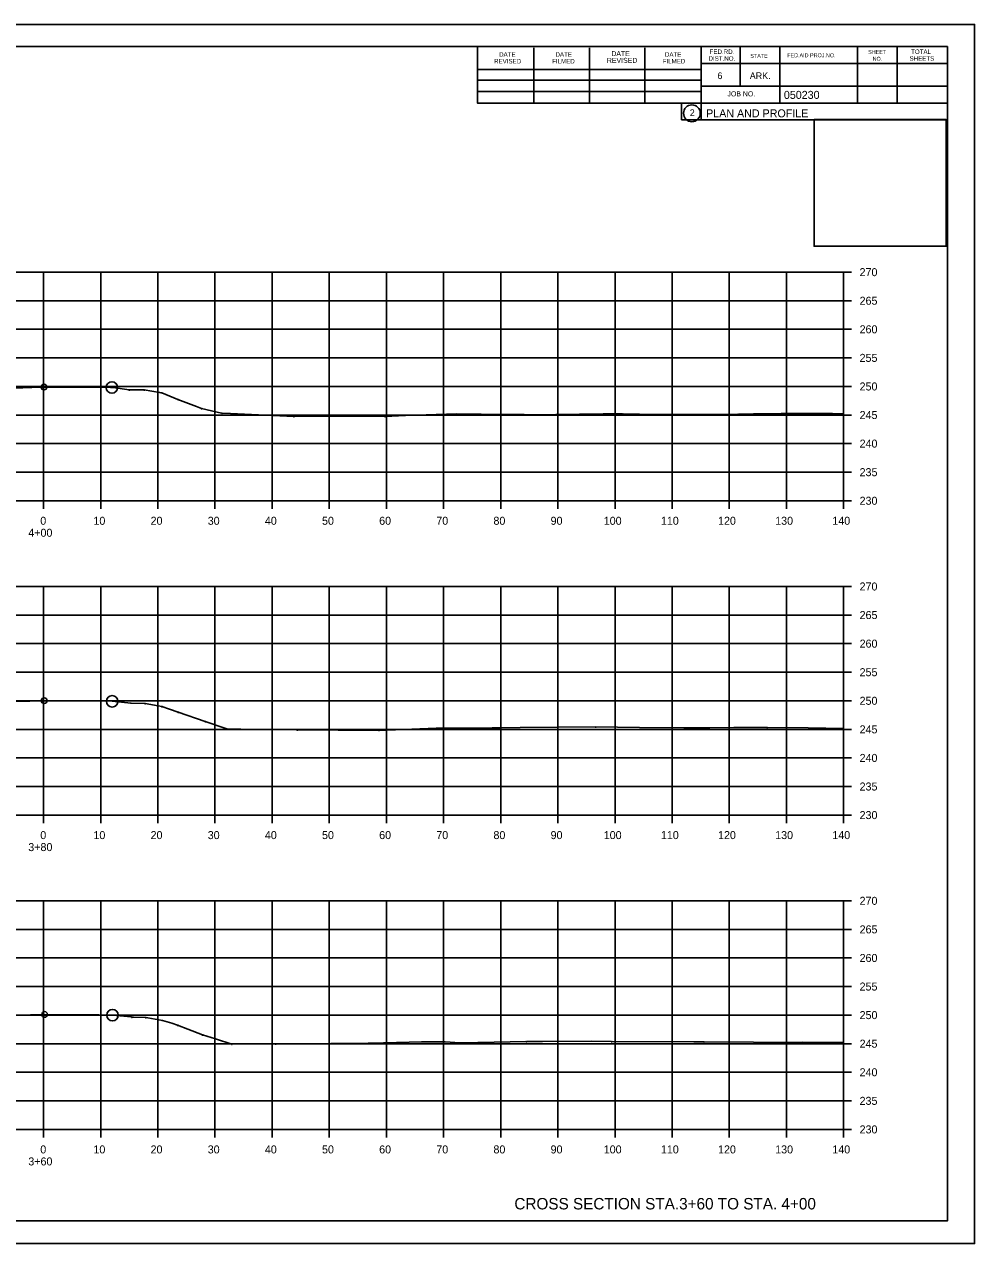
# Model space of a CAD drawing. Extents: x 1300404 to 1323571, y 234004 to 252077.
# Drawn here: x 1315713.9 to 1315880.2, y 241275.1 to 241488.4 of the extents above; entities that cross this region are included whole.
import ezdxf

# ---------------------------------------------------------------- set-up
doc = ezdxf.new("R2010")
doc.units = 0
for name, color, linetype in [('Default', 7, 'Continuous'), ('R_Axis', 7, 'Continuous'), ('R_Axis Annot', 7, 'Continuous'), ('R_Border', 7, 'Continuous'), ('R_Border Prem', 7, 'Continuous'), ('R_Draft', 7, 'Continuous'), ('R_Exist Surface', 7, 'Continuous'), ('R_Grid', 7, 'Continuous'), ('R_No Plot', 7, 'Continuous')]:
    doc.layers.add(name, color=color, linetype=linetype)

msp = doc.modelspace()

# ---------------------------------------------------------------- linework, layer by layer
at = {"layer": 'Default'}
for p, q in [((1315559.28, 241484.55), (1315875.46, 241484.55)), ((1315793.2, 241474.67), (1315793.2, 241484.55)), ((1315803.06, 241474.67), (1315803.06, 241484.35)), ((1315812.82, 241474.67), (1315812.82, 241484.35)), ((1315822.5, 241474.67), (1315822.5, 241484.35)), ((1315832.36, 241484.55), (1315832.36, 241471.75)), ((1315839.2, 241484.55), (1315839.2, 241477.61)), ((1315846.14, 241484.55), (1315846.14, 241474.67)), ((1315859.72, 241484.55), (1315859.72, 241474.67)), ((1315866.66, 241484.55), (1315866.66, 241474.67)), ((1315875.46, 241279.09), (1315875.46, 241484.55)), ((1315875.46, 241481.61), (1315832.36, 241481.61)), ((1315875.46, 241481.63), (1315875.46, 241481.63)), ((1315793.2, 241480.53), (1315832.36, 241480.53)), ((1315793.2, 241478.67), (1315832.36, 241478.67)), ((1315875.46, 241477.61), (1315832.36, 241477.61)), ((1315835.32, 241477.61), (1315875.46, 241477.61)), ((1315793.2, 241474.67), (1315793.2, 241476.73)), ((1315793.2, 241476.73), (1315832.36, 241476.73)), ((1315875.46, 241474.67), (1315793.2, 241474.67)), ((1315832.36, 241471.75), (1315875.46, 241471.75)), ((1315875.46, 241279.09), (1315559.28, 241279.09))]:
    msp.add_line(p, q, dxfattribs=at)
msp.add_circle((1315830.74, 241472.89), 1.47, dxfattribs=at)
at = {"layer": 'R_Axis'}
for p, q in [((1315857.28, 241405.09), (1315857.28, 241445.09)), ((1315858.68, 241445.09), (1315857.28, 241445.09)), ((1315858.68, 241440.09), (1315857.28, 241440.09)), ((1315858.68, 241435.09), (1315857.28, 241435.09)), ((1315858.68, 241430.09), (1315857.28, 241430.09)), ((1315858.68, 241425.09), (1315857.28, 241425.09)), ((1315858.68, 241420.09), (1315857.28, 241420.09)), ((1315858.68, 241415.09), (1315857.28, 241415.09)), ((1315858.68, 241410.09), (1315857.28, 241410.09)), ((1315577.28, 241405.09), (1315857.28, 241405.09)), ((1315717.28, 241403.69), (1315717.28, 241405.09)), ((1315727.28, 241403.69), (1315727.28, 241405.09)), ((1315737.28, 241403.69), (1315737.28, 241405.09)), ((1315747.28, 241403.69), (1315747.28, 241405.09)), ((1315757.28, 241403.69), (1315757.28, 241405.09)), ((1315767.28, 241403.69), (1315767.28, 241405.09)), ((1315777.28, 241403.69), (1315777.28, 241405.09)), ((1315787.28, 241403.69), (1315787.28, 241405.09)), ((1315797.28, 241403.69), (1315797.28, 241405.09)), ((1315807.28, 241403.69), (1315807.28, 241405.09)), ((1315817.28, 241403.69), (1315817.28, 241405.09)), ((1315827.28, 241403.69), (1315827.28, 241405.09)), ((1315837.28, 241403.69), (1315837.28, 241405.09)), ((1315847.28, 241403.69), (1315847.28, 241405.09)), ((1315857.28, 241403.69), (1315857.28, 241405.09)), ((1315858.68, 241405.09), (1315857.28, 241405.09)), ((1315857.28, 241350.09), (1315857.28, 241390.09)), ((1315858.68, 241390.09), (1315857.28, 241390.09)), ((1315858.68, 241385.09), (1315857.28, 241385.09)), ((1315858.68, 241380.09), (1315857.28, 241380.09)), ((1315858.68, 241375.09), (1315857.28, 241375.09)), ((1315858.68, 241370.09), (1315857.28, 241370.09)), ((1315858.68, 241365.09), (1315857.28, 241365.09)), ((1315858.68, 241360.09), (1315857.28, 241360.09)), ((1315858.68, 241355.09), (1315857.28, 241355.09)), ((1315577.28, 241350.09), (1315857.28, 241350.09)), ((1315717.28, 241348.69), (1315717.28, 241350.09)), ((1315727.28, 241348.69), (1315727.28, 241350.09)), ((1315737.28, 241348.69), (1315737.28, 241350.09)), ((1315747.28, 241348.69), (1315747.28, 241350.09)), ((1315757.28, 241348.69), (1315757.28, 241350.09)), ((1315767.28, 241348.69), (1315767.28, 241350.09)), ((1315777.28, 241348.69), (1315777.28, 241350.09)), ((1315787.28, 241348.69), (1315787.28, 241350.09)), ((1315797.28, 241348.69), (1315797.28, 241350.09)), ((1315807.28, 241348.69), (1315807.28, 241350.09)), ((1315817.28, 241348.69), (1315817.28, 241350.09)), ((1315827.28, 241348.69), (1315827.28, 241350.09)), ((1315837.28, 241348.69), (1315837.28, 241350.09)), ((1315847.28, 241348.69), (1315847.28, 241350.09)), ((1315857.28, 241348.69), (1315857.28, 241350.09)), ((1315858.68, 241350.09), (1315857.28, 241350.09)), ((1315857.28, 241295.09), (1315857.28, 241335.09)), ((1315858.68, 241335.09), (1315857.28, 241335.09)), ((1315858.68, 241330.09), (1315857.28, 241330.09)), ((1315858.68, 241325.09), (1315857.28, 241325.09)), ((1315858.68, 241320.09), (1315857.28, 241320.09)), ((1315858.68, 241315.09), (1315857.28, 241315.09)), ((1315858.68, 241310.09), (1315857.28, 241310.09)), ((1315858.68, 241305.09), (1315857.28, 241305.09)), ((1315858.68, 241300.09), (1315857.28, 241300.09)), ((1315577.28, 241295.09), (1315857.28, 241295.09)), ((1315717.28, 241293.69), (1315717.28, 241295.09)), ((1315727.28, 241293.69), (1315727.28, 241295.09)), ((1315737.28, 241293.69), (1315737.28, 241295.09)), ((1315747.28, 241293.69), (1315747.28, 241295.09)), ((1315757.28, 241293.69), (1315757.28, 241295.09)), ((1315767.28, 241293.69), (1315767.28, 241295.09)), ((1315777.28, 241293.69), (1315777.28, 241295.09)), ((1315787.28, 241293.69), (1315787.28, 241295.09)), ((1315797.28, 241293.69), (1315797.28, 241295.09)), ((1315807.28, 241293.69), (1315807.28, 241295.09)), ((1315817.28, 241293.69), (1315817.28, 241295.09)), ((1315827.28, 241293.69), (1315827.28, 241295.09)), ((1315837.28, 241293.69), (1315837.28, 241295.09)), ((1315847.28, 241293.69), (1315847.28, 241295.09)), ((1315857.28, 241293.69), (1315857.28, 241295.09)), ((1315858.68, 241295.09), (1315857.28, 241295.09))]:
    msp.add_line(p, q, dxfattribs=at)
at = {"layer": 'R_Draft'}
for points in [[(1315732.28, 241424.53), (1315732.33, 241424.43), (1315732.23, 241424.43)], [(1315734.91, 241424.53), (1315734.96, 241424.43), (1315734.86, 241424.43)], [(1315737.88, 241424.05), (1315737.93, 241423.95), (1315737.83, 241423.95)], [(1315740.8, 241422.86), (1315740.85, 241422.76), (1315740.75, 241422.76)], [(1315744.9, 241421.28), (1315744.95, 241421.18), (1315744.85, 241421.18)], [(1315748.51, 241420.46), (1315748.56, 241420.36), (1315748.46, 241420.36)], [(1315761.09, 241419.89), (1315761.14, 241419.79), (1315761.04, 241419.79)], [(1315777.03, 241419.89), (1315777.08, 241419.79), (1315776.98, 241419.79)], [(1315802.78, 241420.2), (1315802.83, 241420.1), (1315802.73, 241420.1)], [(1315818.61, 241420.35), (1315818.66, 241420.25), (1315818.56, 241420.25)], [(1315831.09, 241420.24), (1315831.14, 241420.14), (1315831.04, 241420.14)], [(1315838.89, 241420.29), (1315838.94, 241420.19), (1315838.84, 241420.19)], [(1315846.38, 241420.38), (1315846.43, 241420.28), (1315846.33, 241420.28)], [(1315732.57, 241369.75), (1315732.62, 241369.65), (1315732.52, 241369.65)], [(1315735.05, 241369.66), (1315735.1, 241369.56), (1315735, 241369.56)], [(1315737.98, 241369.13), (1315738.03, 241369.03), (1315737.93, 241369.03)], [(1315740.82, 241368.16), (1315740.87, 241368.06), (1315740.77, 241368.06)], [(1315745.57, 241366.51), (1315745.62, 241366.41), (1315745.52, 241366.41)], [(1315749.37, 241365.26), (1315749.42, 241365.16), (1315749.32, 241365.16)], [(1315761.69, 241365.03), (1315761.74, 241364.93), (1315761.64, 241364.93)], [(1315775.96, 241364.97), (1315776.01, 241364.87), (1315775.91, 241364.87)], [(1315786.01, 241365.33), (1315786.06, 241365.23), (1315785.96, 241365.23)], [(1315797.31, 241365.43), (1315797.36, 241365.33), (1315797.26, 241365.33)], [(1315813.88, 241365.56), (1315813.93, 241365.46), (1315813.83, 241365.46)], [(1315829.38, 241365.42), (1315829.43, 241365.32), (1315829.33, 241365.32)], [(1315843.91, 241365.46), (1315843.96, 241365.36), (1315843.86, 241365.36)], [(1315732.74, 241314.8), (1315732.79, 241314.7), (1315732.69, 241314.7)], [(1315735.16, 241314.74), (1315735.21, 241314.64), (1315735.11, 241314.64)], [(1315738.07, 241314.22), (1315738.12, 241314.12), (1315738.02, 241314.12)], [(1315740.74, 241313.39), (1315740.79, 241313.29), (1315740.69, 241313.29)], [(1315745.11, 241311.67), (1315745.16, 241311.57), (1315745.06, 241311.57)], [(1315783.49, 241310.49), (1315783.54, 241310.39), (1315783.44, 241310.39)], [(1315801.78, 241310.52), (1315801.83, 241310.42), (1315801.73, 241310.42)], [(1315816.68, 241310.53), (1315816.73, 241310.43), (1315816.63, 241310.43)], [(1315832.86, 241310.47), (1315832.91, 241310.37), (1315832.81, 241310.37)], [(1315750.23, 241310.07), (1315750.28, 241309.97), (1315750.18, 241309.97)], [(1315757.88, 241310.1), (1315757.93, 241310), (1315757.83, 241310)], [(1315774.11, 241310.23), (1315774.16, 241310.13), (1315774.06, 241310.13)], [(1315790.11, 241310.27), (1315790.16, 241310.17), (1315790.06, 241310.17)], [(1315844.82, 241310.37), (1315844.87, 241310.27), (1315844.77, 241310.27)]]:
    msp.add_lwpolyline(points, close=True, dxfattribs=at)
at = {"layer": 'R_Exist Surface'}
for points in [[(1315705.46, 241424.57), (1315716.84, 241424.98), (1315717.36, 241424.99), (1315728.98, 241424.92), (1315729.24, 241424.91), (1315729.44, 241424.89), (1315732.28, 241424.48), (1315734.18, 241424.49), (1315734.91, 241424.48), (1315737.59, 241424.05), (1315737.88, 241424), (1315737.98, 241423.97), (1315740.8, 241422.81), (1315744.06, 241421.57), (1315744.9, 241421.23), (1315747.65, 241420.61), (1315748.39, 241420.44), (1315748.51, 241420.41), (1315749.99, 241420.35), (1315761.09, 241419.84), (1315765.71, 241419.9), (1315777.03, 241419.84), (1315780.64, 241419.98), (1315787.79, 241420.26), (1315788.33, 241420.26), (1315789.48, 241420.28), (1315798.31, 241420.2), (1315800.27, 241420.17), (1315801.38, 241420.17), (1315802.78, 241420.15), (1315815.18, 241420.32), (1315818.61, 241420.3), (1315824.57, 241420.19), (1315831.09, 241420.19), (1315835.53, 241420.19), (1315838.89, 241420.24), (1315841.54, 241420.3), (1315846.38, 241420.33), (1315855.35, 241420.33), (1315857.28, 241420.3)], [(1315709.82, 241369.88), (1315717.41, 241370.11), (1315721.95, 241370.07), (1315729.29, 241370), (1315732.56, 241369.7), (1315732.57, 241369.7), (1315732.57, 241369.7), (1315735.05, 241369.61), (1315737.32, 241369.2), (1315737.98, 241369.08), (1315739.33, 241368.6), (1315740.82, 241368.11), (1315745.54, 241366.47), (1315745.57, 241366.46), (1315745.58, 241366.46), (1315749.37, 241365.21), (1315751.81, 241365.12), (1315757.22, 241365.04), (1315761.69, 241364.98), (1315775.89, 241364.92), (1315775.96, 241364.92), (1315776.02, 241364.92), (1315786.01, 241365.28), (1315795.8, 241365.38), (1315797.31, 241365.38), (1315800.66, 241365.43), (1315813.88, 241365.51), (1315821.56, 241365.44), (1315829.38, 241365.37), (1315833.87, 241365.37), (1315838.08, 241365.39), (1315843.91, 241365.41), (1315851.06, 241365.37), (1315857.28, 241365.27)], [(1315705.47, 241314.9), (1315714.97, 241315.15), (1315717.47, 241315.22), (1315726.96, 241315.11), (1315729.35, 241315.08), (1315732.64, 241314.76), (1315732.74, 241314.75), (1315732.79, 241314.75), (1315733.04, 241314.74), (1315735.16, 241314.69), (1315735.51, 241314.63), (1315738.07, 241314.17), (1315739.75, 241313.67), (1315740.74, 241313.34), (1315742.5, 241312.66), (1315745.11, 241311.62), (1315747.38, 241310.92), (1315750.23, 241310.02), (1315753.25, 241310.09), (1315757.88, 241310.05), (1315759.11, 241310.04), (1315767.58, 241310.15), (1315774.11, 241310.18), (1315774.38, 241310.18), (1315774.54, 241310.19), (1315783.49, 241310.44), (1315787.57, 241310.41), (1315790.11, 241310.22), (1315793.28, 241310.32), (1315801.78, 241310.47), (1315802.56, 241310.47), (1315804.61, 241310.48), (1315813.1, 241310.51), (1315816.68, 241310.48), (1315831.1, 241310.42), (1315832.86, 241310.42), (1315841.51, 241310.34), (1315844.82, 241310.32), (1315850.02, 241310.35), (1315857.28, 241310.29)]]:
    msp.add_lwpolyline(points, dxfattribs=at)
at = {"layer": 'R_Grid'}
for p, q in [((1315577.28, 241445.09), (1315857.28, 241445.09)), ((1315717.28, 241405.09), (1315717.28, 241445.09)), ((1315727.28, 241405.09), (1315727.28, 241445.09)), ((1315737.28, 241405.09), (1315737.28, 241445.09)), ((1315747.28, 241405.09), (1315747.28, 241445.09)), ((1315757.28, 241405.09), (1315757.28, 241445.09)), ((1315767.28, 241405.09), (1315767.28, 241445.09)), ((1315777.28, 241405.09), (1315777.28, 241445.09)), ((1315787.28, 241405.09), (1315787.28, 241445.09)), ((1315797.28, 241405.09), (1315797.28, 241445.09)), ((1315807.28, 241405.09), (1315807.28, 241445.09)), ((1315817.28, 241405.09), (1315817.28, 241445.09)), ((1315827.28, 241405.09), (1315827.28, 241445.09)), ((1315837.28, 241405.09), (1315837.28, 241445.09)), ((1315847.28, 241405.09), (1315847.28, 241445.09)), ((1315857.28, 241405.09), (1315857.28, 241445.09)), ((1315577.28, 241440.09), (1315857.28, 241440.09)), ((1315577.28, 241435.09), (1315857.28, 241435.09)), ((1315577.28, 241430.09), (1315857.28, 241430.09)), ((1315577.28, 241425.09), (1315857.28, 241425.09)), ((1315577.28, 241420.09), (1315857.28, 241420.09)), ((1315577.28, 241415.09), (1315857.28, 241415.09)), ((1315577.28, 241410.09), (1315857.28, 241410.09)), ((1315577.28, 241405.09), (1315857.28, 241405.09)), ((1315577.28, 241390.09), (1315857.28, 241390.09)), ((1315717.28, 241350.09), (1315717.28, 241390.09)), ((1315727.28, 241350.09), (1315727.28, 241390.09)), ((1315737.28, 241350.09), (1315737.28, 241390.09)), ((1315747.28, 241350.09), (1315747.28, 241390.09)), ((1315757.28, 241350.09), (1315757.28, 241390.09)), ((1315767.28, 241350.09), (1315767.28, 241390.09)), ((1315777.28, 241350.09), (1315777.28, 241390.09)), ((1315787.28, 241350.09), (1315787.28, 241390.09)), ((1315797.28, 241350.09), (1315797.28, 241390.09)), ((1315807.28, 241350.09), (1315807.28, 241390.09)), ((1315817.28, 241350.09), (1315817.28, 241390.09)), ((1315827.28, 241350.09), (1315827.28, 241390.09)), ((1315837.28, 241350.09), (1315837.28, 241390.09)), ((1315847.28, 241350.09), (1315847.28, 241390.09)), ((1315857.28, 241350.09), (1315857.28, 241390.09)), ((1315577.28, 241385.09), (1315857.28, 241385.09)), ((1315577.28, 241380.09), (1315857.28, 241380.09)), ((1315577.28, 241375.09), (1315857.28, 241375.09)), ((1315577.28, 241370.09), (1315857.28, 241370.09)), ((1315577.28, 241365.09), (1315857.28, 241365.09)), ((1315577.28, 241360.09), (1315857.28, 241360.09)), ((1315577.28, 241355.09), (1315857.28, 241355.09)), ((1315577.28, 241350.09), (1315857.28, 241350.09)), ((1315577.28, 241335.09), (1315857.28, 241335.09)), ((1315717.28, 241295.09), (1315717.28, 241335.09)), ((1315727.28, 241295.09), (1315727.28, 241335.09)), ((1315737.28, 241295.09), (1315737.28, 241335.09)), ((1315747.28, 241295.09), (1315747.28, 241335.09)), ((1315757.28, 241295.09), (1315757.28, 241335.09)), ((1315767.28, 241295.09), (1315767.28, 241335.09)), ((1315777.28, 241295.09), (1315777.28, 241335.09)), ((1315787.28, 241295.09), (1315787.28, 241335.09)), ((1315797.28, 241295.09), (1315797.28, 241335.09)), ((1315807.28, 241295.09), (1315807.28, 241335.09)), ((1315817.28, 241295.09), (1315817.28, 241335.09)), ((1315827.28, 241295.09), (1315827.28, 241335.09)), ((1315837.28, 241295.09), (1315837.28, 241335.09)), ((1315847.28, 241295.09), (1315847.28, 241335.09)), ((1315857.28, 241295.09), (1315857.28, 241335.09)), ((1315577.28, 241330.09), (1315857.28, 241330.09)), ((1315577.28, 241325.09), (1315857.28, 241325.09)), ((1315577.28, 241320.09), (1315857.28, 241320.09)), ((1315577.28, 241315.09), (1315857.28, 241315.09)), ((1315577.28, 241310.09), (1315857.28, 241310.09)), ((1315577.28, 241305.09), (1315857.28, 241305.09)), ((1315577.28, 241300.09), (1315857.28, 241300.09)), ((1315577.28, 241295.09), (1315857.28, 241295.09))]:
    msp.add_line(p, q, dxfattribs=at)
at = {"layer": 'R_No Plot'}
for p, q in [((1315546.87, 241488.45), (1315880.21, 241488.45)), ((1315546.87, 241275.11), (1315880.21, 241275.11))]:
    msp.add_line(p, q, dxfattribs=at)
for points in [[(1315546.87, 241488.45), (1315880.21, 241488.45), (1315880.21, 241275.11), (1315546.87, 241275.11)], [(1315793.2, 241484.55), (1315793.2, 241474.67), (1315828.93, 241474.67), (1315828.93, 241471.75), (1315852.13, 241471.75), (1315852.13, 241449.63), (1315875.46, 241449.63), (1315875.46, 241279.09), (1315559.28, 241279.09), (1315559.28, 241484.55)], [(1315852.13, 241471.78), (1315875.23, 241471.78), (1315875.23, 241449.63), (1315852.13, 241449.63)]]:
    msp.add_lwpolyline(points, close=True, dxfattribs=at)
for centre, radius in [((1315729.24, 241424.91), 1), ((1315717.36, 241424.99), 0.5), ((1315717.41, 241370.11), 0.5), ((1315729.29, 241370), 1), ((1315717.47, 241315.22), 0.5), ((1315729.35, 241315.08), 1)]:
    msp.add_circle(centre, radius, dxfattribs=at)

# ---------------------------------------------------------------- texts
at = {"layer": 'Default'}
msp.add_text('2', height=1.17, dxfattribs=at).set_placement((1315830.36, 241472.4))
at = {"layer": 'R_Axis Annot'}
for s, p in [('270', (1315860.08, 241444.39)), ('265', (1315860.08, 241439.39)), ('260', (1315860.08, 241434.39)), ('255', (1315860.08, 241429.39)), ('250', (1315860.08, 241424.39)), ('245', (1315860.08, 241419.39)), ('240', (1315860.08, 241414.39)), ('235', (1315860.08, 241409.39)), ('230', (1315860.08, 241404.39)), ('0', (1315716.71, 241400.89)), ('10', (1315726.01, 241400.89)), ('20', (1315736.01, 241400.89)), ('30', (1315746.01, 241400.89)), ('40', (1315756.01, 241400.89)), ('50', (1315766.01, 241400.89)), ('60', (1315776.01, 241400.89)), ('70', (1315786.01, 241400.89)), ('80', (1315796.01, 241400.89)), ('90', (1315806.01, 241400.89)), ('100', (1315815.31, 241400.89)), ('110', (1315825.31, 241400.89)), ('120', (1315835.31, 241400.89)), ('130', (1315845.31, 241400.89)), ('140', (1315855.31, 241400.89)), ('4+00', (1315714.61, 241398.79)), ('270', (1315860.08, 241389.39)), ('265', (1315860.08, 241384.39)), ('260', (1315860.08, 241379.39)), ('255', (1315860.08, 241374.39)), ('250', (1315860.08, 241369.39)), ('245', (1315860.08, 241364.39)), ('240', (1315860.08, 241359.39)), ('235', (1315860.08, 241354.39)), ('230', (1315860.08, 241349.39)), ('0', (1315716.71, 241345.89)), ('10', (1315726.01, 241345.89)), ('20', (1315736.01, 241345.89)), ('30', (1315746.01, 241345.89)), ('40', (1315756.01, 241345.89)), ('50', (1315766.01, 241345.89)), ('60', (1315776.01, 241345.89)), ('70', (1315786.01, 241345.89)), ('80', (1315796.01, 241345.89)), ('90', (1315806.01, 241345.89)), ('100', (1315815.31, 241345.89)), ('110', (1315825.31, 241345.89)), ('120', (1315835.31, 241345.89)), ('130', (1315845.31, 241345.89)), ('140', (1315855.31, 241345.89)), ('3+80', (1315714.61, 241343.79)), ('270', (1315860.08, 241334.39)), ('265', (1315860.08, 241329.39)), ('260', (1315860.08, 241324.39)), ('255', (1315860.08, 241319.39)), ('250', (1315860.08, 241314.39)), ('245', (1315860.08, 241309.39)), ('240', (1315860.08, 241304.39)), ('235', (1315860.08, 241299.39)), ('230', (1315860.08, 241294.39)), ('0', (1315716.71, 241290.89)), ('10', (1315726.01, 241290.89)), ('20', (1315736.01, 241290.89)), ('30', (1315746.01, 241290.89)), ('40', (1315756.01, 241290.89)), ('50', (1315766.01, 241290.89)), ('60', (1315776.01, 241290.89)), ('70', (1315786.01, 241290.89)), ('80', (1315796.01, 241290.89)), ('90', (1315806.01, 241290.89)), ('100', (1315815.31, 241290.89)), ('110', (1315825.31, 241290.89)), ('120', (1315835.31, 241290.89)), ('130', (1315845.31, 241290.89)), ('140', (1315855.31, 241290.89)), ('3+60', (1315714.61, 241288.79))]:
    msp.add_text(s, height=1.4, dxfattribs=at).set_placement(p)
at = {"layer": 'R_Border'}
for s, height, p in [('DATE', 0.782, (1315797, 241482.79)), ('DATE', 0.782, (1315806.86, 241482.79)), ('DATE', 0.879, (1315816.64, 241482.89)), ('DATE', 0.782, (1315826.02, 241482.79)), ('FED.RD.', 0.782, (1315833.84, 241483.27)), ('STATE', 0.684, (1315840.96, 241482.59)), ('FED.AID PROJ.NO.', 0.684, (1315847.42, 241482.69)), ('SHEET', 0.684, (1315861.58, 241483.27)), ('TOTAL', 0.782, (1315869.1, 241483.27)), ('REVISED', 0.782, (1315796.12, 241481.61)), ('FILMED', 0.782, (1315806.28, 241481.61)), ('REVISED', 0.879, (1315815.86, 241481.71)), ('FILMED', 0.782, (1315825.62, 241481.61)), ('DIST.NO.', 0.782, (1315833.64, 241482.09)), ('NO.', 0.684, (1315862.36, 241482.09)), ('SHEETS', 0.782, (1315868.82, 241482.09)), ('6', 1.17, (1315835.2, 241478.87)), ('ARK.', 1.172, (1315840.86, 241478.87)), ('JOB NO.', 0.879, (1315836.96, 241475.85))]:
    msp.add_text(s, height=height, dxfattribs=at).set_placement(p)
for s, p in [('050230', (1315846.83, 241475.41)), ('PLAN AND PROFILE', (1315833.22, 241472.18))]:
    msp.add_text(s, height=1.4, rotation=360, dxfattribs=at).set_placement(p)
at = {"layer": 'R_Border Prem'}
msp.add_text('DWB', height=0.01, dxfattribs=at).set_placement((1315836.15, 241466.06))
at = {"layer": 'R_Draft'}
msp.add_text('CROSS SECTION STA.3+60 TO STA. 4+00', height=2, dxfattribs=at).set_placement((1315799.67, 241281.09))

doc.saveas('drawing.dxf')
